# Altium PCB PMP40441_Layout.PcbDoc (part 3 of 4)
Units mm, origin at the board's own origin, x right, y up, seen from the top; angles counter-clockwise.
Board outline 66.04 x 61.04 mm, 4 copper layers (Top Layer, Layer 2, Layer 3, Bottom Layer), stack 2.028 mm thick; 208 components, 122 nets, 788 pads, 545 vias.
Unrouted connection lines stored in the file: 24.
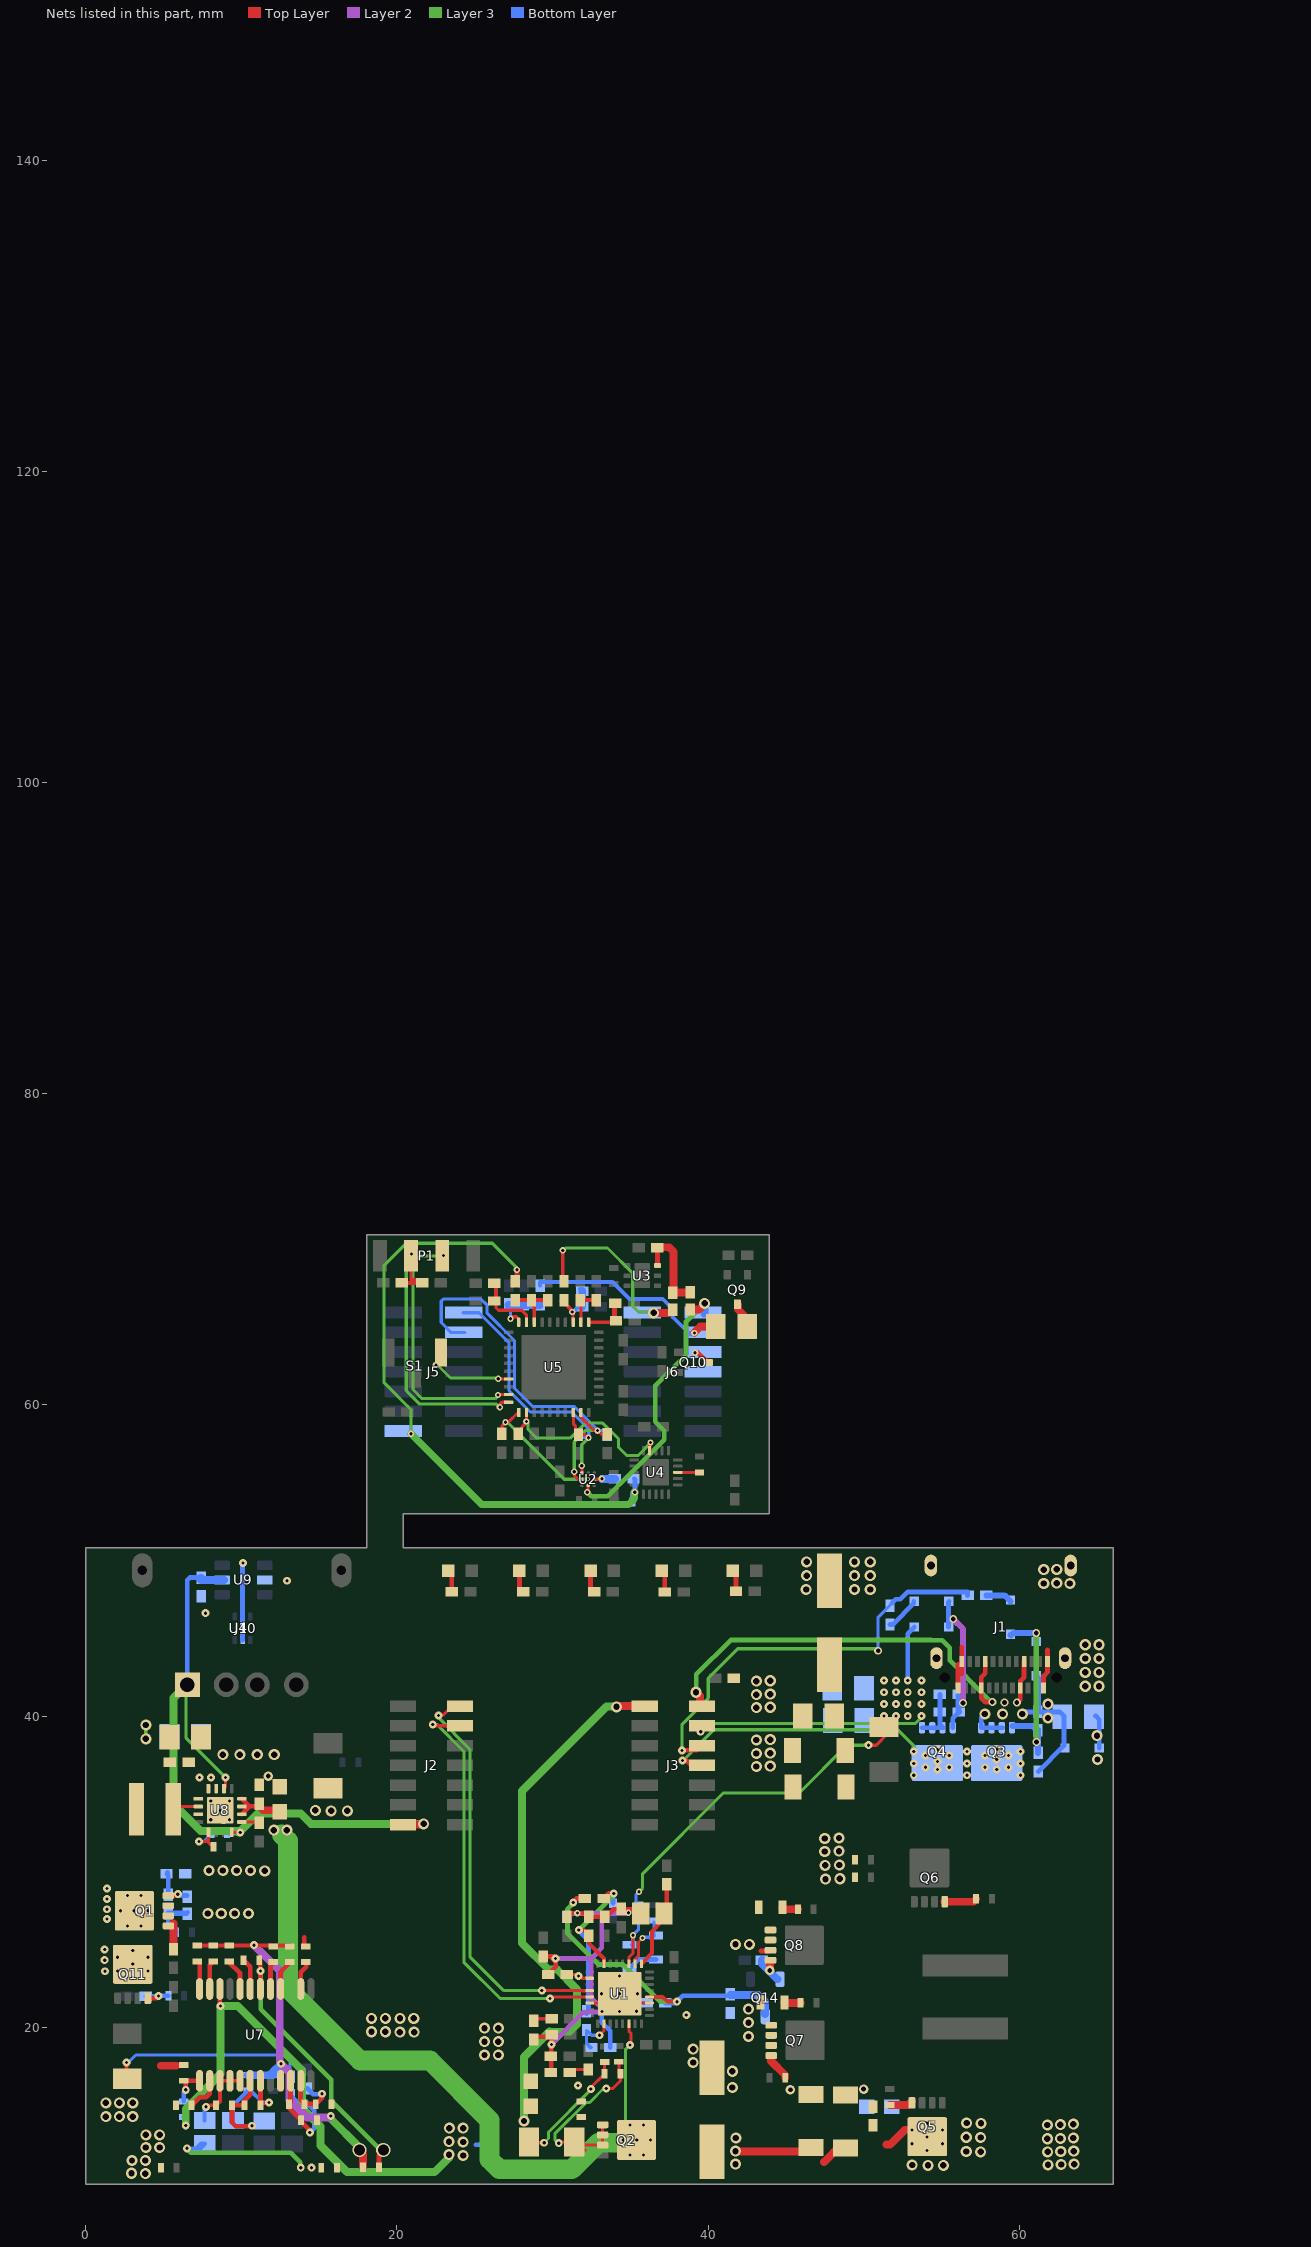
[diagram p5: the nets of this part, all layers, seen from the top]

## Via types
v1: diameter 0.711, hole 0.406, Top Layer to Bottom Layer, 205 vias
v2: diameter 0.508, hole 0.203, Top Layer to Bottom Layer, 152 vias
v3: diameter 0.406, hole 0.203, Top Layer to Bottom Layer, 67 vias
v4: diameter 0.5, hole 0.2, Top Layer to Bottom Layer, 66 vias
v5: diameter 0.508, hole 0.305, Top Layer to Bottom Layer, 16 vias
v6: diameter 0.61, hole 0.305, Top Layer to Bottom Layer, 16 vias
v7: diameter 0.403, hole 0.203, Top Layer to Bottom Layer, 9 vias
v8: diameter 0.5, hole 0.2, Top Layer to Bottom Layer, tented both sides, 6 vias
v9: diameter 0.5, hole 0.2, Top Layer to Bottom Layer, tented top, 5 vias
v10: diameter 0.914, hole 0.711, Top Layer to Bottom Layer, 2 vias
v11: diameter 0.229, hole 0.152, Top Layer to Bottom Layer, 1 vias

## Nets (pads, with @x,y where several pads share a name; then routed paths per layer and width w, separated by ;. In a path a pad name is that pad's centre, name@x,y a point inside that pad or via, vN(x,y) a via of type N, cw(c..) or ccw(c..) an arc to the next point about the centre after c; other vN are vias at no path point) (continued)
NetC11_1: C11.1 R3.2 U1.2 | length 3.5
  Top Layer w0.203: U1.2@35.308,24.074 35.308,24.379 35.527,24.598 35.527,25.476 v7(35.781,25.73)
  Bottom Layer w0.203: v7@35.814,25.781 36.449,25.781 36.551,25.883 36.525,25.908 R3.2@36.525,26.756
NetC12_2: C12.2 R6.2 U1.3 | length 3.6
  Top Layer w0.203: U1.3@34.908,24.074 34.908,24.482 35.171,24.746 v7(35.171,25.908)
  Bottom Layer w0.203: C12.2@35.077,25.298 35.154,25.375 35.154,25.908 35.535,26.289 R6.2@35.535,26.781
NetC13_2: C13.2 R8.2 U1.1 | length 5.8
  Top Layer w0.254: U1.1@35.708,24.074 36.39,24.757 36.39,26.162 36.975,26.746 36.975,27.29 C13.2@37.077,27.392
  Top Layer w0.305: C13.2@37.169,27.301 37.342,27.474 R8.2@37.342,29.189
NetC15_1: C15.1 D4.2 D7.2 Q3.4 R9.2 | length 12.5
  Layer 3 w0.381: v5(61.087,45.339) 61.087,38.354 v5(61.112,38.329)
  Bottom Layer w0.381: D7.2@59.436,45.212 59.461,45.187 59.614,45.339 v5(61.087,45.339) D4.2@61.087,44.788 ; Q3.4@59.563,39.37 60.833,39.37 61.128,39.075 C15.1@61.189,39.075 ; R9.2@61.214,37.633 C15.1@61.214,39.116
NetC21_2: C21.2 D2.1 D3.1 U3.6 | length 6
  Top Layer w0.305: U3.6@36.748,68.951 C21.2@36.748,70.098
  Top Layer w0.508: C21.2@36.728,70.129 37.49,70.129 37.786,69.833 37.786,67.225 D2.1@38.862,67.225
NetC23_1: C23.1 U4.3 | length 1.3
  Top Layer w0.203: U4.3@38.151,55.651 C23.1@39.446,55.651
NetC24_1: C24.1 R26.2 U5.1 | length 3
  Top Layer w0.203: U5.1@32.328,65.312 33.969,65.312 33.985,65.329 R26.2@34.036,65.38
  Top Layer w0.254: R26.2@33.985,65.329 R26.2@34.087,65.329
  Top Layer w0.305: C24.1@33.985,66.523 33.985,65.5 R26.2@34.081,65.405
NetC27_1: C27.1 R27.2 U5.2 | length 2.6
  Top Layer w0.203: C27.1@31.826,66.7 31.828,66.699 31.828,66.597 U5.2@31.828,65.312
  Top Layer w0.254: C27.1@31.75,66.675 C27.1@31.828,66.597 ; C27.1@31.76,66.735 R27.2@32.817,66.735
NetC28_2: C28.2 R28.1 R30.2 U5.3 | length 3.3
  Top Layer w0.203: v3(31.267,65.964) 31.328,65.904 U5.3@31.328,65.312
  Top Layer w0.254: R28.1@30.582,66.675 30.632,66.675 30.861,66.446 30.883,66.446 31.166,66.164 31.166,66.142 31.328,65.98 v3@31.328,65.904
  Bottom Layer w0.254: v3@31.267,65.938 C28.2@31.598,66.269 ; R30.2@31.75,67.437 R30.2@31.785,67.402
  Bottom Layer w0.5: C28.2@31.877,66.294 31.912,66.329 R30.2@31.912,67.31
NetC30_1: C30.1 R33.1 U5.9 | length 4
  Top Layer w0.203: C30.1@26.365,66.675 26.365,66.243 26.527,66.081 28.026,66.081 28.321,65.786 U5.9@28.321,65.405 ; U5.9@28.328,65.312 U5.9@28.328,65.405
  Top Layer w0.254: C30.1@26.365,66.675 R33.1@26.365,67.666
NetC33_2: C33.2 R23.1 R24.2 U5.8 | length 3.1
  Top Layer w0.254: R24.2@27.737,66.726 28.6,66.726 28.61,66.735 R23.1@29.566,66.735 ; U5.8@28.828,65.312 C33.2@28.828,66.626
NetC96_1: C96.1 R1.1 U7.3 U7.4 U7.5 | length 4.5
  Top Layer w0.254: v2(7.722,14.884) 7.823,14.986 C96.1@8.382,14.986 8.636,15.24 8.636,16.561 U7.5@9.982,16.561
  Bottom Layer w0.254: R1.1@7.645,14.009 v2@7.645,14.808
NetC96_2: C96.2 C97.1 R47.1 U7.6 | length 5
  Top Layer w0.305: C96.2@9.398,14.961 9.398,13.894 9.652,13.64 10.668,13.64 v2(10.693,13.665) ; C96.2@9.398,14.986 C97.1@10.16,14.986 ; C97.1@10.211,14.986 10.211,15.291 10.566,15.646 U7.6@10.566,16.612
NetC97_2: C97.2 C98.1 R53.1 U7.7 | length 6.1
  Top Layer w0.254: C97.2@11.328,15.138 11.76,15.138 v2(11.786,15.164) 11.869,15.164 v2@11.887,15.182 ; v2@11.887,15.164 v2@11.887,15.182 ; v2@11.913,15.207 v2@11.887,15.182
  Top Layer w0.305: C97.2@11.227,14.961 C97.2@11.227,14.986 U7.7@11.227,16.434
  Bottom Layer w0.254: R53.1@9.474,14.009 9.474,14.961 C98.1@10.439,15.926 ; C98.1@10.439,15.977 10.566,15.977 11.379,15.164 v2(11.786,15.164)
NetC99_1: C99.1 U7.2 | length 2.3
  Top Layer w0.305: C99.1@6.807,14.986 7.315,15.494 7.747,15.494 7.976,15.723 U7.2@7.976,16.561
NetC102_1: C102.1 C104.2 R62.1 U7.10 | length 7.3
  Top Layer w0.305: U7.10@13.157,16.51 13.157,15.138 C102.1@13.056,15.037 13.056,14.834 C104.2@13.894,13.995 ; C104.2@13.919,13.995 13.919,13.868 14.364,13.424 14.364,13.271 v2(14.402,13.233)
  Bottom Layer w0.305: R62.1@13.157,15.631 13.675,15.113 14.224,15.113 14.681,14.656 14.681,13.513 v2(14.402,13.233)
NetC102_2: C102.2 C105.1 R63.1 U7.11 | length 4.2
  Top Layer w0.305: U7.11@13.818,16.535 13.818,15.291 C102.2@14.072,15.037 ; C102.2@14.097,15.062 14.757,15.062 C105.1@14.783,15.037 ; C105.1@14.808,15.088 15.189,15.469 v2(15.189,15.723)
  Bottom Layer w0.305: R63.1@14.249,16.062 14.615,15.697 15.164,15.697 v2(15.189,15.723)
NetC103_1: C103.1 R45.1 U7.1 | length 2.4
  Top Layer w0.305: C103.1@6.169,16.557 C103.1@6.299,16.557 ; v2(6.426,15.977) C103.1@6.426,16.557 ; C103.1@6.426,16.561 C103.1@6.426,16.557 ; U7.1@7.322,16.557 C103.1@6.426,16.557
  Bottom Layer w0.305: R45.1@6.299,15.24 6.299,15.85 v2(6.426,15.977)
NetC106_2: C106.2 U8.9 | length 1.1
  Top Layer w0.203: U8.9@10.036,33.184 11.104,33.184 C106.2@11.151,33.137
NetC119_2: C119.2 C125.1 Q2.1 Q2.2 Q2.3 R73.1 R78.2 | length 12
  Top Layer w0.203: v2(30.404,12.548) 30.404,12.573 30.455,12.624 R73.1@31.397,12.624 R73.1@31.722,12.299 ; R73.1@31.722,12.426 Q2.3@33.222,12.426 Q2.2@33.222,13.076 Q2.1@33.222,13.726 ; 32.08,12.09 32.08,12.123 ; v2(33.452,16.053) 33.858,16.053 34.366,16.561 C119.2@34.366,17.018 ; R78.2@34.265,17.78 34.265,17.069 C119.2@34.341,16.993
  Layer 3 w0.203: v2@30.404,12.522 v2@30.378,12.548 ; v2(30.404,12.548) v2@30.378,12.548 ; v2@33.452,16.027 33.249,16.027 32.385,15.164 32.156,15.164 30.15,13.157 30.15,12.776 v2@30.378,12.548
NetC130_2: C130.2 R82.2 | length 1
  Top Layer w0.508: R82.2@44.773,27.688 44.876,27.584 C130.2@45.771,27.584
NetC131_2: C131.2 R83.2 | length 1.1
  Top Layer w0.508: R83.2@44.9,21.592 44.925,21.567 C131.2@45.941,21.567
NetC143_1: C143.1 R86.1 | length 1
  Top Layer w0.203: C143.1@28.932,20.549 R86.1@29.948,20.549
NetC144_1: C144.1 R87.1 | length 1.3
  Top Layer w0.203: R87.1@31.098,17.094 31.285,17.282 C144.1@32.301,17.282
NetC145_2: C145.2 D6.2 D8.2 Q4.4 R119.2 | length 9.6
  Layer 2 w0.381: v5(55.753,46.228) 56.388,45.593 v5@56.388,40.894
  Bottom Layer w0.305: D6.2@55.456,45.72 55.456,47.328 D8.2@55.499,47.371 ; Q4.4@55.728,39.254 55.728,39.853 C145.2@56.134,40.259
  Bottom Layer w0.381: R119.2@56.099,41.402 56.099,40.294 C145.2@56.134,40.259
  other v5: 56.388,40.843
NetD5_2: D5.2 Q8.4 Q14.2 | length 2.1
  Top Layer w0.508: v6(43.967,23.647) Q8.4@43.967,24.155
  Bottom Layer w0.508: D5.2@43.451,24.308 43.451,24.085 Q14.2@44.45,23.086
NetD7_1: D7.1 R22.1 | length 1.7
  Bottom Layer w0.381: R22.1@57.877,47.752 59.055,47.752 D7.1@59.436,47.371
NetD8_1: D8.1 R122.1 | length 2.2
  Bottom Layer w0.305: R122.1@51.689,45.882 51.851,45.882 53.213,47.244 D8.1@53.213,47.371
NetD9_1: D9.1 Q1.4 R5.1 R18.2 | length 3.6
  Top Layer w0.305: Q1.4@5.31,28.458 5.979,28.458 5.918,28.518 v2(5.918,28.55)
  Bottom Layer w0.305: R5.1@5.207,29.87 5.309,29.769 R18.2@5.309,28.515 ; R18.2@5.258,28.524 5.283,28.499 R18.2@5.31,28.499 ; R5.1@5.258,29.947 R5.1@5.271,29.934 ; R18.2@5.31,28.458 R18.2@5.31,28.499 ; R18.2@5.309,28.515 R18.2@5.31,28.499 ; v2(5.918,28.55) v2@5.969,28.499 ; D9.1@6.528,28.473 5.994,28.473 v2@5.969,28.499 ; R18.2@5.31,28.499 v2@5.969,28.499
NetD9_2: D9.2 R18.1 R57.1 | length 3.9
  Bottom Layer w0.305: R18.1@5.232,27.305 5.292,27.365 D9.2@6.426,27.365 ; R57.1@5.817,26.111 5.309,26.619 R18.1@5.309,27.315 6.487,27.315 D9.2@6.553,27.381
NetD12_1: D12.1 R100.1 | length 1.4
  Top Layer w0.305: D12.1@23.304,49.34 23.53,49.113 R100.1@23.53,47.993
NetD13_1: D13.1 R101.1 | length 1.5
  Top Layer w0.305: D13.1@27.876,49.34 27.876,48.245 R101.1@28.127,47.993
NetD14_1: D14.1 R102.1 | length 1.4
  Top Layer w0.305: D14.1@32.448,49.34 32.448,48.219 R102.1@32.674,47.993
NetD15_1: D15.1 R103.1 | length 1.5
  Top Layer w0.305: D15.1@37.02,49.34 37.221,49.139 R103.1@37.221,47.968
NetD16_1: D16.1 R104.1 | length 1.4
  Top Layer w0.305: D16.1@41.592,49.34 41.793,49.139 R104.1@41.793,48.019
NetQ1_5: Q1.5 Q1.6 Q1.7 Q1.8 Q1.9@3.135,27.483 Q11.5 Q11.6 Q11.7 Q11.8 Q11.9@3.023,24.043
  other v2: 1.245,23.597 1.219,24.308 1.219,24.994 1.372,26.949 1.372,27.584 1.372,28.245 1.372,28.905
  other v4: 3.023,23.181 2.048,23.619 3.998,23.619 3.023,24.057 2.048,24.495 3.998,24.495 2.683,26.508 3.559,26.508 3.121,27.483 3.997,27.483 2.683,28.458 3.559,28.458
  other v8: 3.023,24.933 2.245,27.483
NetQ5_4: Q5.4 R77.1 | length 1.5
  Top Layer w0.305: Q5.4@53.098,15.236 Q5.4@53.102,15.239
  Top Layer w0.508: R77.1@51.689,15.011 52.867,15.011 Q5.4@53.095,15.239
NetQ6_4: Q6.4 R76.2 | length 2.1
  Top Layer w0.508: Q6.4@55.204,28.066 57.047,28.066 R76.2@57.226,28.245
NetQ7_4: Q7.4 R81.1 | length 1.8
  Top Layer w0.508: Q7.4@44.044,18.136 44.044,17.831 44.958,16.916 R81.1@44.958,16.764
NetQ9_3: Q9.3 R7.1 | length 1.7
  Top Layer w0.508: Q9.3@41.91,66.446 41.91,66.142 42.52,65.532 R7.1@42.52,65.024
NetQ11_4: Q11.4 R4.1 R55.2 | length 2.2
  Top Layer w0.305: Q11.4@3.998,21.868 4.571,21.868 v2@4.699,21.996
  Bottom Layer w0.305: R4.1@3.861,21.996 v2@4.648,21.996 ; v2@4.674,22.022 R55.2@5.309,22.022
  other v2: 4.674,21.996
NetR1_2: R1.2 R34.1 | length 10.6
  Layer 3 w0.305: v2@6.477,12.217 6.756,11.938 13.183,11.938 13.792,11.328 13.792,10.973 v2@13.818,10.947
  Bottom Layer w0.305: v2@6.502,12.192 R1.2@7.112,12.192 ; v2@6.553,12.141 7.061,12.141 R1.2@7.112,12.192 ; R1.2@7.112,12.192 7.329,12.192 R1.2@7.645,12.509 7.429,12.509 R1.2@7.112,12.192
  other v2: 13.818,10.973 14.503,10.973 6.502,12.217
NetR10_1: R10.1 U2.B1 | length 1.3
  Top Layer w0.203: U2.B1@32.69,55.22 v3@33.198,55.22
  Bottom Layer w0.508: v3(33.172,55.245) R10.1@34.004,55.245
NetR11_1: R11.1 U7.24 | length 1.8
  Top Layer w0.305: R11.1@7.163,24.232 7.322,24.073 U7.24@7.322,22.457
NetR12_1: R12.1 U7.23 | length 1.9
  Top Layer w0.305: U7.23@7.972,22.457 7.972,23.999 R12.1@8.204,24.232
NetR13_1: R13.1 U7.20 | length 2.1
  Top Layer w0.305: R13.1@9.195,24.206 9.195,24.181 9.922,23.454 U7.20@9.922,22.457
NetR14_1: R14.1 R59.2 U7.18 | length 17.9
  Top Layer w0.305: R14.1@11.176,24.282 11.222,24.237 U7.18@11.222,22.457 ; R59.2@18.847,10.998 18.847,11.76 v10@19.126,12.04
  Layer 3 w0.305: v2@11.252,23.622 11.252,21.158 15.773,16.637 15.773,15.265 18.923,12.116 v10(19.126,12.116)
  other v2: 11.227,23.622
NetR14_2: R14.2 U7.19 | length 2
  Top Layer w0.305: R14.2@10.185,24.257 10.572,23.871 U7.19@10.572,22.457
NetR15_1: R15.1 U7.14 | length 1.9
  Top Layer w0.305: U7.14@13.822,22.457 13.822,23.542 14.173,23.893 R15.1@14.173,24.206
NetR16_1: R16.1 U7.16 | length 1.9
  Top Layer w0.305: U7.16@12.522,22.457 12.522,23.571 R16.1@13.106,24.155
NetR17_1: R17.1 U7.17 | length 1.8
  Top Layer w0.305: U7.17@11.872,22.457 11.872,23.937 R17.1@12.065,24.13
NetR93_1: R93.1 R95.2 U1.18 | length 3.4
  Top Layer w0.203: v2@33.02,19.482 33.308,19.769 U1.18@33.308,20.224
  Bottom Layer w0.203: R93.1@32.182,19.787 32.182,19.018 ; R93.1@32.233,19.761 32.512,19.482 v2(33.012,19.482) ; R95.2@32.436,18.669 32.182,18.923 32.182,19.018 ; R95.2@32.506,18.694 32.182,19.018 ; v2@33.016,19.478 v2@33.02,19.482
NetR99_1: R99.1 U1.10 | length 1.6
  Top Layer w0.203: R99.1@30.92,23.394 31.654,23.394 31.898,23.149 U1.10@32.383,23.149
  other v2: 31.666,23.292
NetR105_1: R105.1 R106.2 U8.5 | length 2.6
  Top Layer w0.203: v2(7.29,31.928) 7.706,31.928 7.782,32.004 7.886,31.9 ; U8.5@7.886,32.534 7.886,31.9 ; R106.2@8.112,31.674 7.886,31.9
  Bottom Layer w0.203: v2@7.29,31.902 7.544,31.902 7.985,32.344 R105.1@7.985,32.461
NetS1_1: S1.1 U5.17 | length 5.1
  Top Layer w0.203: v3(26.518,61.671) 26.527,61.662 U5.17@27.178,61.662
  Layer 3 w0.203: v3(22.504,62.56) 22.606,62.56 23.444,61.722 26.467,61.722 v3(26.518,61.671) v3@26.543,61.646
PD_INTb: R31.2 U2.B2 U5.21 | length 8.8
  Top Layer w0.203: R31.2@26.746,58.131 26.746,58.623 v3@27,58.877 ; v3(26.975,58.877) v3@27,58.877 ; U5.21@27.813,59.538 27.153,58.877 v3@27,58.877
  Layer 3 w0.203: v3(26.975,58.877) 27.107,58.877 28.123,57.861 28.123,57.856 30.759,55.22 v11(32.283,55.22)
PGND: C2.2 C4.1 C5.1 C6.2 C8.2 C9.2 C10.2 C11.2 C12.1 C13.1 C14.1 C17.2 C107.2 C114.2 C115.2 C116.2 C120.2 C121.2 C122.2 C123.2 C124.2 C125.2 C126.2 C127.1 C128.1 C132.1 C135.1 C136.2 C137.2 C140.2 C142.1 C143.2 C151.1 C152.2 C153.2 D1.2 J1.A1 J1.A12 J1.B1 J1.B12 J1.S1 J1.S2 J1.S3 J1.S4 NT1.2 Q1.1 Q1.2 Q1.3 Q7.1 Q7.2 Q7.3 Q8.1 Q8.2 Q8.3 R5.2 R15.2 R19.1 R82.1 R83.1 R87.2 R94.2 R95.1 R98.2 R99.2 R112.1 U1.14 U1.27 U1.33@34.308,22.149 U8.15 U8.16 U8.17@8.636,33.934 U9.2 U10.2 U10.5 | length 51.8
  Top Layer w0.203: U1.14@32.383,21.549 U1.33@33.36,21.549 ; U1.33@35.316,21.549 U1.27@36.233,21.549
  Top Layer w0.305: 14.046,25.781 14.046,25.298 R15.2@14.148,25.197 ; C143.2@28.796,19.212 28.964,19.38 29.743,19.38 29.921,19.558 29.921,17.069 R87.2@29.896,17.043 ; C153.2@29.405,24.546 29.861,24.546 ; R99.2@29.693,23.368 R99.2@29.719,23.394 ; R99.2@29.72,23.394 30.201,23.874 v2(30.201,24.409) ; v2@30.099,24.308 29.861,24.546 ; v2@30.188,24.397 30.038,24.546 29.861,24.546 ; R98.2@30.937,27.051 31.217,27.33 v7(31.598,27.33) 32.131,27.33 C137.2@32.369,27.092 ; C137.2@32.336,27.092 C137.2@32.369,27.092 ; R94.2@33.36,27.092 C137.2@32.369,27.092 ; R94.2@33.401,27.051 33.934,27.584 35.357,27.584 C13.1@35.738,27.203 ; 43.383,24.892 43.952,24.892 Q8.3@44.01,24.95 ; J1.A12@56.059,41.81 56.059,43.334 ; 56.309,42.7 J1.B1@56.309,43.51 56.309,44.447 ; J1.A1@61.559,41.81 61.559,42.585 61.57,42.596 ; 61.62,42.621 61.809,42.81 J1.B12@61.809,43.51 61.809,44.258
  Top Layer w0.508: C4.1@5.639,25.009 Q1.1@5.639,26.67
  Layer 2 w0.305: v2(29.939,18.898) 32.021,20.98 v2@33.198,20.98 ; v2(30.201,24.409) 32.334,24.409 32.487,24.257 ; v7@31.615,27.305 34.824,27.305 v7(34.874,27.356) ; v2@33.172,21.006 33.172,21.209 32.487,21.895 32.487,24.257 ; 33.172,27.28 33.172,25.095 32.487,24.409 32.487,24.257
  Bottom Layer w0.305: U10.5@10.084,44.894 U10.2@10.084,46.394 v2@10.084,49.86 ; C152.2@30.912,27.083 31.14,27.311 31.528,27.311 31.547,27.33 v7(31.598,27.33) ; v2@33.172,21.006 33.172,20.295 33.706,19.761 R95.1@33.706,18.694 ; 34.9,23.266 C12.1@34.9,23.724 ; C12.1@34.9,23.774 C12.1@34.9,23.724 ; C11.2@36.652,24.359 35.535,24.359 C12.1@34.9,23.724 ; C17.2@64.897,40.005 65.133,39.769 D1.2@65.133,37.948
  other v1: 61.849,11.155 62.687,11.176 63.525,11.201 61.824,11.994 62.662,12.014 63.5,12.04 61.798,12.832 62.636,12.852 63.475,12.878 61.798,13.721 62.636,13.741 63.475,13.767 41.554,16.129 41.554,17.17 39.04,17.729 25.629,18.212 26.518,18.212 39.04,18.593 25.629,19.075 26.518,19.075 42.596,19.406 20.19,19.68 21.107,19.685 18.364,19.71 19.253,19.71 25.629,19.939 26.518,19.939 42.596,20.295 18.364,20.574 19.253,20.574 20.193,20.574 21.082,20.574 42.596,21.158 41.758,25.324 42.647,25.324 7.849,27.305 8.712,27.305 9.576,27.305 10.465,27.305 47.549,29.515 48.463,29.54 11.506,30.048 7.925,30.074 8.814,30.074 9.703,30.074 10.592,30.074 47.523,30.404 48.438,30.429 47.498,31.293 48.412,31.318 47.498,32.131 48.412,32.156 15.773,33.909 16.815,33.909 14.757,33.934 43.104,36.754 43.993,36.779 65.024,37.211 8.814,37.516 9.906,37.516 11.024,37.516 12.116,37.516 43.104,37.592 43.993,37.617 43.104,38.456 43.993,38.481 64.999,38.74 43.104,40.538 43.993,40.564 43.104,41.377 43.993,41.402 64.237,41.915 65.126,41.915 43.104,42.24 43.993,42.266 64.237,42.804 65.126,42.804 64.237,43.693 65.126,43.693 64.237,44.582 65.126,44.582 46.304,48.133 49.403,48.133 50.419,48.133 61.57,48.519 63.246,48.514 62.408,48.539 46.33,49.022 49.403,49.022 50.419,49.022 61.57,49.408 62.408,49.428 46.33,49.911 49.403,49.911 50.419,49.911
  other v2: 31.648,16.256 38.6,20.777 33.19,21.006 35.408,21.031 7.315,36.043 8.052,36.043 7.696,46.609 12.929,48.692 10.109,49.835
  other v4: 34.308,20.999 33.158,22.149 34.308,22.149 35.458,22.149 34.308,23.299
  other v6: 45.288,15.977 49.987,16.027 11.735,36.144
  other v9: 8.036,33.334 9.236,33.334 8.636,33.934 8.036,34.534 9.236,34.534
REGN: C14.2 C151.2 Q14.3 R84.2 U1.28 | length 21.4
  Top Layer w0.254: U1.28@36.233,21.943 37.079,21.943 37.381,21.641 v2(37.991,21.641)
  Top Layer w0.305: v2(31.336,28.016) 31.336,28.085 31.522,28.27 R84.2@32.082,28.27
  Layer 3 w0.305: v2(31.336,28.016) 31.336,27.958 30.963,27.584 30.963,26.035 32.969,24.028 34.544,24.028 36.932,21.641 v2@38.024,21.641
  Bottom Layer w0.305: C151.2@37.252,21.565 37.922,21.565 38.379,22.022 41.275,22.022 C14.2@41.402,22.149
  Bottom Layer w0.508: C14.2@41.427,22.063 43.24,22.063 43.663,21.641 Q14.3@43.663,20.848
RST: C32.1 P1.3 R38.1 U5.20 | length 20.8
  Top Layer w0.203: P1.3@20.955,69.672 20.904,69.621 20.904,67.869 20.879,67.843 20.437,67.843 20.463,67.818 R38.1@21.819,67.818 ; v3(26.619,59.842) 26.619,60.05 26.716,60.147 26.732,60.147 26.747,60.162 U5.20@27.178,60.162
  Top Layer w0.254: P1.3@20.92,69.672 P1.3@20.92,69.774 ; 20.955,68.021 R38.1@21.742,68.021
  Layer 3 w0.203: v3@20.93,69.723 20.599,69.393 20.599,60.935 20.676,60.858 20.676,60.838 21.468,60.046 26.391,60.046 26.594,59.842 v3(26.619,59.842)
  other v3: 20.93,69.698
SCL: C31.1 J2.12 J5.12 R36.2 U1.13 U2.B3 U5.29 | length 54.4
  Top Layer w0.203: v2(22.301,39.446) 22.377,39.37 J2.12@24.068,39.37 ; v2(29.845,21.844) 29.947,21.946 U1.13@32.385,21.946 ; v3@31.42,55.677 31.42,55.423 31.623,55.22 U2.B3@31.89,55.22 ; U5.29@31.826,59.538 31.826,59.207 32.664,58.369 v3@32.893,58.369 ; v3(32.893,58.344) v3@32.893,58.369 ; C31.1@33.528,58.106 33.157,58.106 v3@32.893,58.369
  Top Layer w0.305: J2.12@23.991,39.446 24.118,39.573 J2.12@24.195,39.497 ; J2.12@24.068,39.37 J2.12@24.195,39.497 ; J2.12@24.245,39.548 J2.12@24.195,39.497
  Layer 3 w0.203: v2@22.327,39.446 22.581,39.446 24.308,37.719 24.308,24.181 26.645,21.844 v2(29.845,21.844) ; v3(31.394,55.702) 31.394,57.619 32.145,58.369 32.17,58.344 v3(32.893,58.344)
  Bottom Layer w0.203: J5.12@24.384,64.643 23.495,64.643 22.848,65.29 22.848,66.663 22.987,66.802 25.4,66.802 25.781,66.421 25.781,65.913 27.559,64.135 27.559,61.062 28.727,59.893 31.394,59.893 32.893,58.395 v3(32.893,58.344) 33.249,58.344 33.274,58.369 R36.2@33.553,58.09
SDA: C29.1 J2.14 J5.14 R32.2 U1.12 U2.C3 U5.28 | length 46
  Top Layer w0.203: v2@22.708,40.056 22.962,40.056 23.546,40.64 J2.14@24.068,40.64 ; v2(29.312,22.352) U1.12@32.385,22.352 ; U5.28@31.328,59.512 31.344,59.496 31.344,58.776 31.471,58.649 C29.1@31.471,57.988 ; C29.1@31.674,58.08 32.09,58.08 v3@32.309,57.861 ; v3(31.877,56.083) 31.89,56.07 U2.C3@31.89,55.62 ; 31.928,22.349 U1.12@32.383,22.349
  Top Layer w0.305: v2(22.682,40.03) v2@22.708,40.03
  Layer 3 w0.203: v2@22.682,40.005 22.682,39.878 24.689,37.871 24.689,24.536 26.873,22.352 v2(29.312,22.352) ; v3(31.877,56.083) 31.877,57.429 v3@32.309,57.861
  Bottom Layer w0.203: J5.14@24.257,65.913 25.273,65.913 27.203,63.983 27.203,60.914 28.58,59.538 31.247,59.538 32.334,58.451 v3@32.334,57.861 ; R32.2@31.674,58.064 31.826,57.912 32.233,57.912 v3@32.283,57.861 ; v3@32.296,57.899 v3@32.309,57.912
  other v3: 32.309,57.887
SW_A: L5.2 U8.1 U8.2 U8.3 | length 1.4
  Top Layer w0.203: L5.2@5.8,34.184 U8.2@7.236,34.184
TEST: P1.2 U5.19 | length 16.8
  Top Layer w0.203: v3@26.492,60.655 26.499,60.662 U5.19@27.178,60.662
  Layer 3 w0.203: v3@22.962,69.571 21.539,69.571 21.031,69.063 21.031,60.985 21.615,60.401 26.314,60.401 26.518,60.604 v3(26.492,60.63)
  other v3: 22.987,69.596
TPD_FLTb: R25.1 U4.9 U5.22 | length 12.8
  Top Layer w0.203: R25.1@27.788,58.131 27.788,58.318 28.321,58.852 v3(28.321,58.928) ; v3@28.328,58.947 U5.22@28.328,59.512 ; U4.9@36.245,57.059 36.245,57.504 36.347,57.607 36.323,57.583 v3(36.295,57.583)
  Layer 3 w0.203: v3(28.321,58.928) 28.423,58.826 28.423,58.42 28.981,57.861 31.134,57.861 32.099,58.826 33.223,58.826 34.239,57.81 34.239,57.278 34.774,56.744 35.509,56.744 v3@36.322,57.556
VBAT+: C119.1 C126.1 D3.2 J3.2 J6.2 R28.2 R34.2 R45.2 R73.2 R79.2 U7.22 | length 88.1
  Top Layer w0.203: R73.2@28.497,12.624 28.547,12.573 v2(29.464,12.573) ; v2(32.461,16.027) 32.461,16.129 C119.1@33.35,17.018 33.35,17.704 R79.2@33.325,17.729
  Top Layer w0.254: R28.2@30.632,67.935 30.658,67.961 v3(30.658,69.926)
  Top Layer w0.305: v2@8.622,21.423 U7.22@8.622,22.457
  Top Layer w0.508: v1@34.112,40.564 34.188,40.64 J3.2@35.927,40.64 ; v1(36.5,65.913) 37.465,65.913 D3.2@37.719,66.167
  Layer 3 w0.203: v2(29.464,12.573) 29.743,12.852 29.743,13.259 32.436,15.951 v2@32.436,16.027 ; v3@30.683,69.926 30.836,70.079 33.533,70.079 35.154,68.458 35.154,66.345 35.535,65.964 36.449,65.964 v1(36.5,65.913)
  Layer 3 w0.508: v2(6.426,13.691) 6.426,14.757 8.661,16.993 v2(8.661,21.361) 9.773,21.361 13.894,17.241 13.894,14.808 15.088,13.614 15.088,12.395 16.789,10.693 22.428,10.693 23.343,11.608 v1(23.343,11.811) ; v1@28.169,13.995 28.169,18.085 29.806,19.722 ; 29.817,19.71 31.09,19.71 31.572,20.193 31.572,22.428 30.277,23.724 29.718,23.724 28.042,25.4 28.042,35.179 33.477,40.615 v1@34.138,40.615 ; v1@34.125,40.602 v1@34.138,40.589
  Bottom Layer w0.305: R45.2@6.299,14.224 6.426,14.097 v2(6.426,13.691) ; 25.07,12.446 25.814,12.446 25.855,12.487
  Bottom Layer w0.508: v1(36.5,65.913) J6.2@36.525,65.938
  other v1: 24.257,11.76 24.257,12.624 23.343,12.649 23.368,13.513 24.257,13.513 28.169,13.97 34.112,40.589
VBAT-: C1.1 C98.2 C99.2 C103.2 C104.1 C105.2 R11.2 R12.2 R13.2 R16.2 R17.2 R35.2 R59.1 R60.1 R62.2 U7.9 | length 40.6
  Top Layer w0.254: v2(2.616,17.729) 2.616,16.736 R60.1@2.667,16.686 ; R11.2@7.137,25.248 R13.2@9.22,25.248 13.132,25.248 R16.2@13.183,25.197
  Top Layer w0.508: 4.851,17.526 5.817,17.526 ; v10@17.551,12.116 17.831,11.836 R59.1@17.831,10.998
  Layer 2 w0.508: v2(10.82,25.273) 12.471,23.622 12.471,17.729 v2(12.548,17.653) 13.106,17.094 13.106,15.316 14.224,14.199 v2@15.672,14.199
  Layer 3 w0.508: v2@15.748,14.224 15.748,14.122 17.602,12.268 v10(17.602,12.116)
  Bottom Layer w0.203: v2@2.743,17.729 3.226,18.212 12.827,18.212 13.132,17.907 R62.2@13.132,16.815
  Bottom Layer w0.254: v2(2.616,17.729) v2@2.743,17.729
  Bottom Layer w0.508: C98.2@10.414,16.916 C1.1@12.04,16.916 12.04,17.12 v2@12.548,17.628
  other v1: 3.835,10.592 2.946,10.617 2.972,11.43 3.835,11.43 3.861,12.268 4.75,12.268 3.861,13.081 4.75,13.081 1.295,14.249 2.159,14.249 3.023,14.249 1.295,15.138 2.159,15.138 3.023,15.138
  other v2: 15.748,14.3
VBUS: C15.2 C17.1 D1.1 D2.2 D4.1 J1.A4 J1.A9 J1.B4 J1.B9 J3.1 J6.1 Q3.1 Q3.2 Q3.3 R9.1 U2.A2 | length 61.4
  Top Layer w0.203: v3@32.233,54.356 32.29,54.413 U2.A2@32.29,54.82
  Top Layer w0.305: J1.A9@57.556,41.732 57.556,42.494 57.809,42.747 J1.B4@57.809,43.51 ; J1.A9@57.559,41.81 57.559,41.145 57.81,40.894 v5(58.268,40.894) v5@58.293,40.894 ; v5@59.893,40.869 60.059,41.034 J1.A4@60.059,41.81 60.059,42.251 60.302,42.494 60.302,43.513 J1.B9@60.325,43.536
  Top Layer w0.508: D2.2@38.862,66.125 39.43,66.125 v1@39.802,66.497 ; v1(39.218,41.529) 39.472,41.275 J3.1@39.472,40.64
  Layer 3 w0.305: v3(32.233,54.381) 32.487,54.127 33.553,54.127 34.036,54.61 34.036,54.617 34.334,54.915 34.341,54.915 36.501,57.075 36.505,57.075 36.803,57.372 36.803,57.377 37.186,57.76 37.186,58.344 36.601,58.928 36.601,61.239 38.583,63.221 38.583,65.354 v1@39.776,66.548 ; v1@39.243,41.529 39.243,42.672 41.453,44.882 54.32,44.882 54.324,44.877 55.034,44.877 55.536,44.375 55.536,43.575 56.617,42.494 56.617,42.469 ; 56.566,42.52 56.617,42.469 ; v5(58.268,40.894) 58.191,40.894 56.617,42.469
  Bottom Layer w0.305: v1(57.785,40.132) 57.556,39.903 Q3.1@57.556,39.254 Q3.2@58.217,39.254 Q3.3@58.877,39.254 58.917,39.254 Q3.3@58.928,39.243 ; v1(60.198,40.132) 60.325,40.259 62.611,40.259 62.865,40.005 62.865,38.084 R9.1@61.214,36.433
  Bottom Layer w0.381: D4.1@61.087,42.545 61.189,42.443 C15.2@61.189,40.275
  Bottom Layer w0.508: J6.1@39.751,65.862 39.776,65.888 v1(39.776,66.523)
  other v1: 61.849,39.878 58.928,40.132 61.849,40.767
  other v5: 59.055,40.869 59.842,40.869
VBUS1: C116.1 C127.2 C128.2 C132.2 C135.2 C136.1 C145.1 D6.1 J3.3 J6.3 Q4.1 Q4.2 Q4.3 R6.1 R7.2 R72.1 R119.1 R128.2 | length 57.3
  Top Layer w0.203: v2(50.317,38.125) 50.8,38.125 R72.1@51.562,38.887
  Top Layer w0.508: v3@39.116,64.643 39.497,65.024 R7.2@40.488,65.024
  Layer 3 w0.203: v7(35.552,28.702) 35.789,28.939 35.789,29.87 40.97,35.052 45.847,35.052 48.92,38.125 v2(50.317,38.125) v2@50.368,38.125 ; v2@39.497,38.989 40.005,39.497 40.259,39.497 40.284,39.522 53.315,39.522 53.721,39.929 v2(53.721,40.005) ; v2@39.522,38.964 v2@39.7,39.141
  Bottom Layer w0.203: R6.1@35.357,27.965 35.357,28.499 v7@35.56,28.702 ; v2@52.705,42.418 v2(52.832,42.291)
  Bottom Layer w0.254: R128.2@29.21,67.656 29.21,67.889 33.853,67.889 34.941,66.802 37.084,66.802 37.719,66.167 37.719,65.659 38.862,64.516 J6.3@39.116,64.516
  Bottom Layer w0.305: v2(52.832,42.291) 52.832,45.296 D6.1@53.256,45.72 ; Q4.1@53.746,39.254 Q4.2@54.407,39.254 Q4.3@55.067,39.254 Q4.3@55.107,39.254 ; R119.1@54.899,41.402 C145.1@54.899,40.259 54.899,39.462 Q4.3@55.107,39.254 ; Q4.3@55.118,39.243 Q4.3@55.107,39.254
  other v2: 39.522,38.989 51.308,40.005 52.07,40.005 52.832,40.005 51.308,40.767 52.07,40.767 52.832,40.767 53.721,40.767 51.308,41.529 52.07,41.529 52.832,41.529 53.721,41.529 51.308,42.291 52.07,42.291 53.721,42.291
  other v3: 39.116,64.618
VBUS1_1: C108.2 R128.1 R130.2 U5.10 | length 3.9
  Top Layer w0.203: v3(27.305,65.532) 27.432,65.659 27.686,65.659 27.813,65.532 27.813,65.327 U5.10@27.828,65.312
  Bottom Layer w0.203: v3(27.305,65.532) C108.2@27.305,66.548
  Bottom Layer w0.5: C108.2@27.178,66.421 28.194,66.421 R128.1@29.175,66.421 ; R128.1@29.175,66.583 R128.1@29.21,66.548
VDDA: C137.1 R84.1 R92.1 R93.2 U1.7 | length 13.4
  Top Layer w0.254: v2(31.691,26.238) 31.99,26.238 C137.1@32.336,25.892 32.336,25.391 33.308,24.419 U1.7@33.308,24.074
  Top Layer w0.305: R84.1@33.282,28.27 33.612,28.6 v2(33.934,28.6)
  Layer 3 w0.305: v2(31.691,26.238) 33.934,28.481 v2(33.934,28.6)
  Bottom Layer w0.305: v2@31.648,26.238 32.309,25.578 32.309,20.987 R93.2@32.182,20.86 ; R92.1@33.884,27.975 33.884,28.575 v2@33.909,28.6
VGBUS: J3.5 J6.5 Q10.3 R22.2 R122.2 | length 28.5
  Top Layer w0.305: v2(38.329,37.795) 39.268,37.795 J3.5@39.573,38.1 ; v3(39.167,63.348) 39.345,63.348 Q10.3@40.03,62.662
  Layer 3 w0.203: v2(38.329,37.795) 38.329,39.472 40.005,41.148 40.005,42.418 41.91,44.323 50.8,44.323 v5(50.927,44.196)
  Bottom Layer w0.203: v2(38.329,37.795) v2@38.329,37.871 ; v5(50.927,44.196) 50.927,46.355 R122.2@51.816,47.244
  Bottom Layer w0.305: R122.2@51.816,47.244 52.07,47.498 52.352,47.498 52.83,47.976 56.677,47.976 R22.2@56.677,47.752
VO_A: C5.2 C6.1 C8.1 C16.1 C107.1 J2.1 J4.1 J5.1 L5.1 R10.2 R24.1 R105.2 U8.8 U8.14 U9.5 | length 86.8
  Top Layer w0.203: U8.14@8.886,35.334 8.992,35.44 v2(8.992,36.043) ; U8.8@9.408,32.512 v2(9.931,32.512)
  Top Layer w0.305: R24.1@27.711,67.935 v3@27.711,68.631
  Top Layer w0.508: J2.1@20.382,33.02 21.641,33.02 v1@21.692,33.071
  Layer 3 w0.203: v1(3.861,39.421) 3.861,38.913 v1@4.064,38.71 ; J4.1@6.452,41.965 6.452,38.583 v2(8.992,36.043) ; J4.1@6.452,42.037 6.452,42.164 J4.1@6.477,42.189 ; v3(20.904,58.141) 20.904,59.69 19.177,61.417 19.177,68.961 20.599,70.383 26.137,70.383 27.737,68.783 v3@27.737,68.656
  Layer 3 w0.457: v3(20.904,58.141) 25.451,53.594 34.874,53.594 35.281,54 v3@35.281,54.356
  Layer 3 w0.508: J4.1@6.524,42.037 6.452,41.965 5.639,41.152 5.639,34.366 7.391,32.614 9.754,32.614 9.855,32.512 11.074,33.731 13.818,33.731 14.478,33.071 21.742,33.071 v1@21.768,33.045 ; v3@35.281,54.356 v3(35.281,54.381)
  Bottom Layer w0.305: J4.1@6.524,42.037 6.524,48.738 6.68,48.895 C107.1@7.417,48.895 ; R105.2@9.185,32.461 9.881,32.461 v2(9.931,32.512) ; C16.1@35.128,53.772 35.128,54.229 v3(35.281,54.381) 35.306,54.407 35.306,55.194 R10.2@35.255,55.245
  Bottom Layer w0.508: C107.1@7.417,48.885 7.417,48.743 U9.5@8.763,48.743 U9.5@8.887,48.743
  other v1: 21.717,33.071 3.861,38.532
  other v3: 27.711,68.682
VSBUS: J3.7 J6.7 Q3.5 Q3.6 Q3.7 Q3.8 Q3.9@58.547,36.974 Q4.5 Q4.6 Q4.7 Q4.8 Q4.9@54.737,36.974 | length 17.8
  Top Layer w0.305: v2(38.354,37.135) 38.633,37.135 38.964,36.805 J3.7@39.573,36.805
  Layer 3 w0.203: v2(38.354,37.135) 38.387,37.135 40.368,39.116 52.197,39.116 53.213,38.1 v2(53.213,37.719)
  other v2: 53.213,36.195 56.642,36.195 60.071,36.195 53.975,36.703 55.499,36.703 57.785,36.703 59.309,36.703 53.213,36.957 56.642,36.957 60.071,36.957 54.737,37.084 58.547,37.211 53.975,37.465 55.499,37.465 57.785,37.465 59.309,37.465 56.642,37.719 60.071,37.719
  other v4: 54.737,36.569 58.547,36.569 54.737,37.844 58.547,37.844
VSYS: C9.1 C10.1 C120.1 C121.1 C122.1 C123.1 C124.1 Q2.5 Q2.6 Q2.7 Q2.8 Q2.9@35.397,12.751 Q5.5 Q5.6 Q5.7 Q5.8 Q5.9@54.077,12.964 U1.22 U8.10 U8.11 U8.12 | length 59.7
  Top Layer w0.203: U1.22@34.908,20.224 34.908,19.753 35.044,19.616 35.044,18.89 v2@34.976,18.821
  Top Layer w0.305: U8.10@10.036,33.684 10.55,34.198 ; U8.12@10.036,34.684 10.522,34.198 10.55,34.198 ; C10.1@11.151,34.198 10.55,34.198
  Top Layer w0.508: C10.1@11.151,34.198 11.405,33.944 12.471,33.944 C9.1@12.471,33.846 ; Q2.9@35.397,12.751 v4(35.411,12.751) v8(36.287,12.751) ; v1@41.758,12.007 45.761,12.007 ; 47.447,11.33 48.573,12.456 C121.1@49.327,12.456 ; 51.46,12.456 51.699,12.456 52.652,13.409 Q5.9@54.077,13.409
  Layer 3 w0.203: 34.696,13.843 34.696,18.593 v2@34.963,18.86
  Layer 3 w1.27: 12.598,32.385 13.005,31.979 13.005,22.479 17.628,17.856 22.123,17.856 25.959,14.021 25.959,11.506 26.594,10.871 31.242,10.871 32.944,12.573 35.233,12.573
  other v1: 54.127,11.125 55.118,11.125 53.111,11.151 41.758,11.201 57.514,11.994 56.591,12.014 41.758,12.04 41.783,12.878 57.514,12.909 56.591,12.929 57.539,13.823 56.617,13.843 12.09,32.664 12.929,32.664
  other v2: 34.976,18.847
  other v4: 34.973,11.776 35.849,11.776 53.102,12.512 55.052,12.512 34.535,12.751 54.077,12.95 53.102,13.388 55.052,13.388 34.973,13.726 35.849,13.726 54.077,13.826
  other v8: 54.077,12.074
pads on no net: J1.A2 J1.A3 J1.A8 J1.A10 J1.A11 J1.ALIGN1 J1.ALIGN2 J1.B2 J1.B3 J1.B8 J1.B10 J1.B11 Q1.9@2.61,26.508 Q1.9@2.61,27.158 Q1.9@2.61,27.808 Q1.9@2.61,28.458 Q1.9@3.121,26.82 Q1.9@3.121,28.145 Q1.9@3.457,27.483 Q1.9@3.997,26.82 Q1.9@3.997,28.145 Q2.9@34.535,12.088 Q2.9@34.535,13.413 Q2.9@35.075,12.751 Q2.9@35.411,12.088 Q2.9@35.411,13.413 Q2.9@35.922,11.776 Q2.9@35.922,12.426 Q2.9@35.922,13.076 Q2.9@35.922,13.726 Q3.9@56.997,37.914 Q3.9@57.977,37.329 Q3.9@58.547,37.179 Q3.9@58.547,37.914 Q3.9@59.117,37.329 Q3.9@60.097,37.914 Q4.9@53.187,37.914 Q4.9@54.167,37.329 Q4.9@54.737,37.179 Q4.9@54.737,37.914 Q4.9@55.307,37.329 Q4.9@56.287,37.914 Q5.9@53.102,12.439 Q5.9@53.414,12.95 Q5.9@53.414,13.826 Q5.9@53.752,12.439 Q5.9@54.077,13.287 Q5.9@54.402,12.439 Q5.9@54.739,12.95 Q5.9@54.739,13.826 Q5.9@55.052,12.439 Q6.9@53.254,30.766 Q6.9@53.567,29.379 Q6.9@53.567,30.255 Q6.9@53.904,30.766 Q6.9@54.229,29.918 Q6.9@54.554,30.766 Q6.9@54.892,29.379 Q6.9@54.892,30.255 Q6.9@55.204,30.766 Q7.9@45.373,18.491 Q7.9@45.373,19.816 Q7.9@45.913,19.154 Q7.9@46.76,18.179 Q7.9@46.76,18.829 Q7.9@46.76,19.479 Q7.9@46.76,20.129 Q7.9@46.249,18.491 Q7.9@46.249,19.816 Q8.9@45.323,24.612 Q8.9@45.323,25.937 Q8.9@45.862,25.275 Q8.9@46.71,24.3 Q8.9@46.71,24.95 Q8.9@46.71,25.6 Q8.9@46.71,26.25 Q8.9@46.199,24.612 Q8.9@46.199,25.937 Q11.9@2.36,23.181 Q11.9@2.36,24.057 Q11.9@2.048,24.568 Q11.9@2.698,24.568 Q11.9@3.023,23.721 Q11.9@3.348,24.568 Q11.9@3.685,23.181 Q11.9@3.685,24.057 Q11.9@3.998,24.568 U1.11 U1.15 U1.33@33.593,21.434 U1.33@33.593,22.864 U1.33@35.023,21.434 U1.33@35.023,22.864 U3.2 U3.4 U3.5 U3.7@35.773,67.851 U3.7@35.773,68.751 U4.1 U4.2 U4.14 U4.15 U4.21@36.17,55.184 U4.21@36.17,56.134 U4.21@37.12,55.184 U4.21@37.12,56.134 U5.6 U5.7 U5.15 U5.16 U5.18 U5.24 U5.25 U5.30 U5.33 U5.34 U5.35 U5.38 U5.41@28.708,61.042 U5.41@28.708,62.412 U5.41@28.708,63.782 U5.41@30.078,61.042 U5.41@30.078,62.412 U5.41@30.078,63.782 U5.41@31.448,61.042 U5.41@31.448,62.412 U5.41@31.448,63.782 U7.15 U7.21 U8.4 U8.17@8.636,33.934 U9.3 U9.4
copper on no net: | length 0.1
  Bottom Layer w0.305: 54.909,37.699 54.909,37.756

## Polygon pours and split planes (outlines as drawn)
GND_A on Top Layer "GND_A_L01_P224" (solid, remove dead copper, pour order 224): 12.776,43.18 12.37,42.774 12.37,39.167 14.3,37.236 14.859,37.236 15.316,37.694 16.002,37.694 16.561,37.135 16.586,37.16 17.094,37.16 17.551,37.617 17.526,37.643 17.526,41.377 15.723,43.18
AGND on Top Layer "AGND_L01_P347" (solid, remove dead copper, pour order 347): 19.172,70.631 18.41,69.869 18.41,54.451 19.527,53.334 42.819,53.334 43.607,54.121 43.607,70.148 43.124,70.631
PGND on Top Layer "Top Layer-No Net 26" (solid, remove dead copper, pour order 275): 40.403,46.842 38.329,44.768 38.329,32.567 34.341,28.579 34.341,19.71 29.235,19.71 29.235,16.078 30.556,14.757 50.495,14.757 51.156,15.418 51.156,17.221 50.267,18.11 46.38,18.11 46.076,18.415 45.872,18.618 44.602,18.618 44.602,28.194 44.856,28.448 49.124,28.448 49.682,29.007 49.682,33.223 49.39,33.515 48.196,33.515 46.711,35.001 46.711,45.415 45.283,46.842
AGND on Top Layer "AGND_L01_P229" (solid, remove dead copper, pour order 229): 20.777,42.697 18.466,40.386 18.466,32.715 19.406,31.775 40.64,31.775 41.326,32.461 41.326,41.834 40.462,42.697
NetQ1_5 on Top Layer "NETQ1_5_L01_P235" (solid, remove dead copper, pour order 235): 0.914,29.337 0.279,28.702 0.279,22.962 0.559,22.682 4.267,22.682 4.47,22.885 4.47,28.727 3.861,29.337
VBAT- on Top Layer "Top Layer-No Net 10" (solid, remove dead copper, pour order 257): 3.251,18.034 4.877,18.034 5.105,17.805 5.105,13.437 5.105,12.014 5.105,10.744 4.586,10.224 0.838,10.211 0.279,10.77 0.279,17.678 0.635,18.034 1.905,18.034 2.134,17.805 2.134,17.526 2.337,17.323 2.616,17.323 2.87,17.323 3.023,17.475 3.023,17.805
PGND on Top Layer "Top Layer-No Net 25" (solid, remove dead copper, pour order 274): 0.279,30.201 0.279,49.301 1.499,50.521 19.914,50.521 20.93,50.521 21.666,49.784 21.666,47.269 22.301,46.634 40.589,46.634 41.681,45.542 41.681,42.926 41.681,32.246 38.576,29.141 38.576,23.336 32.207,16.967 16.561,16.967 16.561,22.835 9.754,29.642 0.838,29.642
PGND on Top Layer "Top Layer-No Net 23" (solid, remove dead copper, pour order 270): 4.064,29.667 4.928,28.804 4.928,26.035 5.131,25.832 14.58,25.832 15.037,26.289 15.037,30.175 14.453,30.759 4.572,30.759 4.064,30.251
PGND on Top Layer "Top Layer-No Net 22" (solid, remove dead copper, pour order 265): 16.561,16.104 16.561,17.155 16.662,17.345 16.662,21.59 28.753,21.59 30.81,19.533 30.81,15.748 16.916,15.748
PGND on Top Layer "Top Layer-No Net 21" (solid, remove dead copper, pour order 264): 29.38,28.118 28.389,27.127 28.389,17.018 28.669,16.739 37.279,16.739 37.279,27.229 36.39,28.118
VO_A on Top Layer "Top Layer-No Net 16" (solid, remove dead copper, pour order 225): 1.651,43.053 1.651,35.738 2.464,34.925 2.464,32.283 2.616,32.131 3.861,32.131 4.039,32.309 4.039,34.925 6.071,36.957 6.071,39.37 7.442,40.742 7.442,43.358 6.807,43.993 2.591,43.993
SW_A on Top Layer "Top Layer-No Net 14" (solid, remove dead copper, pour order 262): 4.953,32.537 4.953,35.535 5.232,35.814 6.121,35.814 6.68,35.255 6.68,35.052 6.934,34.798 7.544,34.798 7.544,33.655 6.198,32.309 5.182,32.309
NetC3_2 on Top Layer "Top Layer-No Net 11" (solid, remove dead copper, pour order 259): 0.229,22.047 0.229,18.771 0.635,18.364 1.854,18.364 1.981,18.491 1.981,18.745 2.287,19.051 2.742,19.051 3.073,18.72 3.073,18.567 3.277,18.364 5.613,18.364 6.071,18.821 6.071,22.352 0.533,22.352
NetC119_2 on Top Layer "Top Layer-No Net 6" (solid, remove dead copper, pour order 253): 30.505,14.478 30.074,14.046 30.074,13.36 30.226,13.208 30.582,13.208 30.785,13.005 30.785,12.751 30.785,12.421 30.505,12.141 30.175,12.141 30.074,12.04 30.074,10.678 30.49,10.262 33.426,10.262 33.63,10.465 33.63,13.995 33.147,14.478
VSYS on Top Layer "Top Layer-No Net 5" (solid, remove dead copper, pour order 252): 59.055,13.407 59.055,10.82 58.471,10.236 34.773,10.236 34.138,10.871 34.138,13.945 34.392,14.199 58.264,14.199
HB_SW2 on Top Layer "Top Layer-No Net 4" (solid, remove dead copper, pour order 250): 62.509,21.895 49.657,21.895 46.05,21.895 44.933,20.777 44.933,17.78 45.263,17.45 45.568,17.45 46.076,16.942 51.867,16.942 54.051,14.757 60.427,14.757 62.941,17.272 62.941,21.463
HB_SW1 on Top Layer "Top Layer-No Net 4" (solid, remove dead copper, pour order 251): 62.56,28.575 50.089,28.575 49.809,28.296 46.203,28.296 44.806,26.899 44.806,23.774 46.203,22.377 62.535,22.377 62.916,22.758 62.916,28.219
AGND on Top Layer "Top Layer-No Net 20" (solid, remove dead copper, pour order 263): 44.044,46.787 44.856,47.6 44.856,49.581 43.917,50.521 22.479,50.521 22.149,50.19 22.149,47.625 22.987,46.787
VBAT- on Top Layer "Top Layer-No Net 10" (solid, remove dead copper, pour order 256): 6.401,18.771 5.41,17.78 5.41,13.106 6.223,12.294 14.808,12.294 16.027,13.513 16.027,17.475 16.027,22.784 13.31,25.502 6.883,25.502 6.401,25.019
VSYS on Top Layer "Top Layer-No Net 28" (solid, remove dead copper, pour order 227): 13.284,32.563 13.284,34.011 12.548,34.747 9.888,34.747 9.779,34.638 9.779,33.503 10.947,32.334 13.056,32.334
CELL1 on Top Layer "Top Layer-No Net 9" (solid, remove dead copper, pour order 254): 8.534,11.405 8.331,11.201 8.331,10.77 8.509,10.592 9.881,10.592 9.906,10.592 10.058,10.744 10.058,11.227 9.881,11.405
VBAT+ on Top Layer "Top Layer-No Net 7" (solid, remove dead copper, pour order 255): 15.926,13.233 15.926,10.998 16.688,10.236 29.489,10.236 29.693,10.439 29.693,11.938 29.489,12.141 29.286,12.141 29.134,12.294 29.134,13.056 29.261,13.183 29.515,13.183 29.693,13.36 29.693,14.808 29.108,15.393 18.085,15.392
CELL_N on Top Layer "Top Layer-No Net 9" (solid, remove dead copper, pour order 281): 6.045,11.405 5.842,11.201 5.842,10.77 6.02,10.592 7.391,10.592 7.417,10.592 7.569,10.744 7.569,11.227 7.391,11.405
CELL2 on Top Layer "Top Layer-No Net 9" (solid, remove dead copper, pour order 287): 10.947,11.379 10.744,11.176 10.744,10.744 10.922,10.566 12.294,10.566 12.319,10.566 12.471,10.719 12.471,11.201 12.294,11.379
NetR1_2 on Top Layer "Top Layer-No Net 9" (solid, remove dead copper, pour order 331): 13.487,11.379 13.284,11.176 13.284,10.744 13.462,10.566 14.834,10.566 14.91,10.566 15.062,10.719 15.062,11.151 14.834,11.379
VSBUS on Top Layer "VSBUS_L01_P367" (solid, remove dead copper, pour order 367): 60.198,38.1 60.452,37.846 60.452,35.941 60.325,35.814 53.086,35.814 52.832,36.068 52.832,37.846 53.086,38.1
CHG_ACN on Top Layer "CHG_ACN_L01_P371" (solid, remove dead copper, pour order 371): 50.546,37.592 52.451,37.592 52.578,37.465 52.578,35.814 52.832,35.56 62.865,35.56 63.246,35.179 63.246,29.464 62.738,28.956 50.292,28.956 50.038,29.21 50.165,29.337 50.165,37.211
VBUS on Top Layer "VBUS_L01_P381" (solid, remove dead copper, pour order 381): 57.404,41.148 62.611,41.148 63.246,40.513 63.246,39.116 62.738,38.608 57.404,38.608 57.15,38.862 57.15,40.894
VBUS1 on Top Layer "VBUS1_L01_P395" (solid, remove dead copper, pour order 395): 46.99,45.085 47.244,45.339 51.054,45.339 54.102,42.291 54.102,39.116 53.213,38.227 49.784,38.227 49.53,37.973 49.53,34.036 49.276,33.782 48.26,33.782 46.99,35.052
PGND on Top Layer "PGND_L01_P397" (solid, remove dead copper, pour order 397): 44.577,46.863 45.085,47.371 45.085,50.292 45.339,50.546 64.897,50.546 65.786,49.657 65.786,10.414 65.532,10.16 44.196,10.16 43.434,10.922 43.434,45.847 43.815,46.228
AGND on Bottom Layer "AGND_L04_P399" (solid, remove dead copper, pour order 399): 18.288,70.104 18.796,70.612 43.053,70.612 43.561,70.104 43.561,54.102 42.672,53.213 19.558,53.213 18.288,54.483
NetC3_2 on Bottom Layer "NETC3_2_L04_P353" (solid, remove dead copper, pour order 353): 0.61,21.641 0.279,21.311 0.279,19.355 0.483,19.152 0.94,19.152 1.118,19.329 1.118,21.438 0.914,21.641
VBAT+ on Bottom Layer "Bottom Layer-No Net 8" (solid, remove dead copper, pour order 244): 23.891,15.102 22.86,14.072 22.86,11.125 23.746,10.239 29.467,10.239 29.769,10.541 29.769,11.839 29.515,12.093 29.356,12.093 29.112,12.337 29.112,12.96 29.286,13.135 29.769,13.135 29.769,14.548 29.279,15.044
CELL1 on Bottom Layer "Top Layer-No Net 9" (solid, remove dead copper, pour order 277): 8.56,11.43 8.331,11.201 8.331,10.77 8.484,10.617 9.887,10.617 9.913,10.617 10.065,10.77 10.065,11.252 9.887,11.43
no net on Bottom Layer "Bottom Layer-No Net 3" (solid, remove dead copper, shelved, pour order 279): 58.801,34.773 50.12,34.773 49.784,34.436 49.784,31.394 50.165,31.013 58.698,31.013 59.157,31.472 59.157,33.667 59.157,34.417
